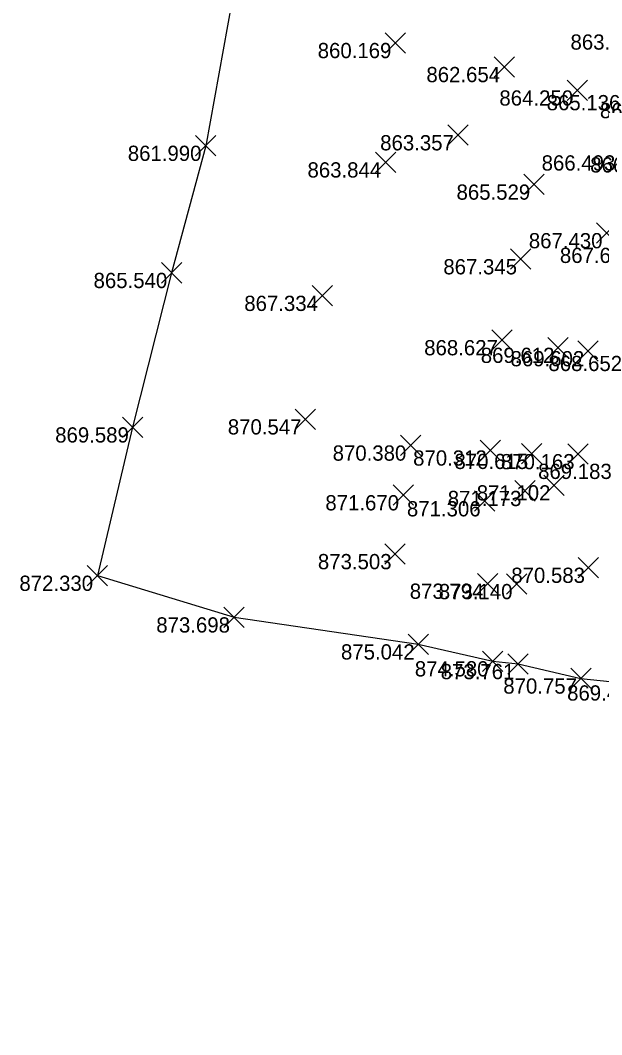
# Model space of a CAD drawing. Extents: x 2228183 to 2230895, y 679226 to 682223.
# Drawn here: x 2228195.6 to 2228233.8, y 680376.3 to 680442.9 of the extents above; entities that cross this region are included whole.
import ezdxf

# ---------------------------------------------------------------- set-up
doc = ezdxf.new("R2010")
doc.units = 0
for name, color, linetype in [('SC_Scratch1', 7, 'Continuous'), ('SV_X_Random_Point', 7, 'Continuous'), ('SV_X_Terrain_Boundary', 7, 'Continuous')]:
    doc.layers.add(name, color=color, linetype=linetype)

msp = doc.modelspace()

# ---------------------------------------------------------------- linework, layer by layer
at = {"layer": 'SV_X_Random_Point'}
for p, q in [((2228219.56, 680440.706), (2228220.894, 680442.041)), ((2228219.56, 680442.041), (2228220.894, 680440.706)), ((2228226.73, 680439.129), (2228228.064, 680440.464)), ((2228226.73, 680440.464), (2228228.064, 680439.129)), ((2228231.511, 680437.592), (2228232.845, 680438.927)), ((2228231.511, 680438.927), (2228232.845, 680437.592)), ((2228223.671, 680434.652), (2228225.005, 680435.987)), ((2228223.671, 680435.987), (2228225.005, 680434.652)), ((2228207.128, 680433.96), (2228208.462, 680435.295)), ((2228207.128, 680435.295), (2228208.462, 680433.96)), ((2228218.927, 680432.871), (2228220.261, 680434.206)), ((2228218.927, 680434.206), (2228220.261, 680432.871)), ((2228228.669, 680431.414), (2228230.003, 680432.749)), ((2228228.669, 680432.749), (2228230.003, 680431.414)), ((2228233.443, 680428.225), (2228234.777, 680429.56)), ((2228233.443, 680429.56), (2228234.777, 680428.225)), ((2228227.79, 680426.514), (2228229.124, 680427.849)), ((2228227.79, 680427.849), (2228229.124, 680426.514)), ((2228204.882, 680425.614), (2228206.216, 680426.949)), ((2228204.882, 680426.949), (2228206.216, 680425.614)), ((2228214.779, 680424.111), (2228216.113, 680425.446)), ((2228214.779, 680425.446), (2228216.113, 680424.111)), ((2228226.559, 680421.2), (2228227.893, 680422.535)), ((2228226.559, 680422.535), (2228227.893, 680421.2)), ((2228230.248, 680420.699), (2228231.582, 680422.034)), ((2228230.248, 680422.034), (2228231.582, 680420.699)), ((2228232.205, 680420.479), (2228233.539, 680421.814)), ((2228232.205, 680421.814), (2228233.539, 680420.479)), ((2228213.672, 680416.003), (2228215.006, 680417.338)), ((2228213.672, 680417.338), (2228215.006, 680416.003)), ((2228202.333, 680415.474), (2228203.667, 680416.809)), ((2228202.333, 680416.809), (2228203.667, 680415.474)), ((2228220.57, 680414.284), (2228221.904, 680415.619)), ((2228220.57, 680415.619), (2228221.904, 680414.284)), ((2228225.81, 680413.959), (2228227.144, 680415.294)), ((2228225.81, 680415.294), (2228227.144, 680413.959)), ((2228228.518, 680413.737), (2228229.852, 680415.072)), ((2228228.518, 680415.072), (2228229.852, 680413.737)), ((2228231.561, 680413.719), (2228232.895, 680415.054)), ((2228231.561, 680415.054), (2228232.895, 680413.719)), ((2228228.073, 680411.304), (2228229.407, 680412.639)), ((2228228.073, 680412.639), (2228229.407, 680411.304)), ((2228229.986, 680411.671), (2228231.32, 680413.006)), ((2228229.986, 680413.006), (2228231.32, 680411.671)), ((2228220.092, 680411.02), (2228221.426, 680412.355)), ((2228220.092, 680412.355), (2228221.426, 680411.02)), ((2228225.434, 680410.627), (2228226.768, 680411.962)), ((2228225.434, 680411.962), (2228226.768, 680410.627)), ((2228219.552, 680407.158), (2228220.886, 680408.493)), ((2228219.552, 680408.493), (2228220.886, 680407.158)), ((2228232.243, 680406.26), (2228233.577, 680407.595)), ((2228232.243, 680407.595), (2228233.577, 680406.26)), ((2228200.015, 680405.736), (2228201.349, 680407.071)), ((2228200.015, 680407.071), (2228201.349, 680405.736)), ((2228225.638, 680405.216), (2228226.972, 680406.551)), ((2228225.638, 680406.551), (2228226.972, 680405.216)), ((2228227.536, 680405.191), (2228228.87, 680406.526)), ((2228227.536, 680406.526), (2228228.87, 680405.191)), ((2228208.983, 680403.002), (2228210.317, 680404.337)), ((2228208.983, 680404.337), (2228210.317, 680403.002)), ((2228221.075, 680401.231), (2228222.409, 680402.566)), ((2228221.075, 680402.566), (2228222.409, 680401.231)), ((2228225.964, 680400.12), (2228227.298, 680401.455)), ((2228225.964, 680401.455), (2228227.298, 680400.12)), ((2228227.629, 680399.94), (2228228.963, 680401.275)), ((2228227.629, 680401.275), (2228228.963, 680399.94)), ((2228231.75, 680398.991), (2228233.084, 680400.326)), ((2228231.75, 680400.326), (2228233.084, 680398.991))]:
    msp.add_line(p, q, dxfattribs=at)
at = {"layer": 'SV_X_Terrain_Boundary'}
for points in [[(2228219.411, 680529.247), (2228217.574, 680519.169), (2228217.809, 680511.512), (2228216.826, 680504.223), (2228214.656, 680486.931), (2228213.909, 680475.664), (2228214.292, 680470.108), (2228212.955, 680461.42), (2228211.821, 680456.822), (2228210.919, 680451.97), (2228207.795, 680434.627), (2228205.549, 680426.281), (2228203, 680416.141), (2228200.682, 680406.403)], [(2228200.682, 680406.403), (2228209.65, 680403.669), (2228221.742, 680401.898), (2228226.631, 680400.787), (2228228.296, 680400.607), (2228232.417, 680399.658), (2228236.631, 680399.204), (2228242.224, 680398.608), (2228245.011, 680398.302), (2228246.89, 680398.302), (2228247.363, 680398.195), (2228248.152, 680398.096), (2228248.769, 680398.124), (2228250.307, 680398.124), (2228256.103, 680397.505), (2228261.512, 680396.621), (2228262.98, 680396.337), (2228264.719, 680396.078), (2228261.054, 680370.168)]]:
    msp.add_lwpolyline(points, dxfattribs=at)

# ---------------------------------------------------------------- texts
at = {"layer": 'SC_Scratch1'}
for s, p in [('863.395', (2228231.73, 680440.932)), ('860.169', (2228215.143, 680440.373)), ('862.654', (2228222.275, 680438.796)), ('864.250', (2228227.064, 680437.259)), ('865.136', (2228230.168, 680436.952)), ('865.402', (2228233.661, 680436.432)), ('863.357', (2228219.242, 680434.319)), ('861.990', (2228202.681, 680433.627)), ('866.493', (2228229.837, 680432.995)), ('866.582', (2228233.024, 680432.868)), ('863.844', (2228214.472, 680432.538)), ('865.529', (2228224.252, 680431.081)), ('867.430', (2228228.996, 680427.892)), ('867.688', (2228231.034, 680426.929)), ('867.345', (2228223.387, 680426.181)), ('865.540', (2228200.435, 680425.281)), ('867.334', (2228210.324, 680423.778)), ('868.627', (2228222.13, 680420.867)), ('869.612', (2228225.842, 680420.366)), ('869.602', (2228227.799, 680420.146)), ('868.652', (2228230.282, 680419.833)), ('870.547', (2228209.243, 680415.67)), ('869.589', (2228197.916, 680415.141)), ('870.380', (2228216.123, 680413.951)), ('870.312', (2228221.404, 680413.626)), ('870.615', (2228224.115, 680413.404)), ('870.163', (2228227.164, 680413.386)), ('869.183', (2228229.605, 680412.749)), ('871.173', (2228223.676, 680410.971)), ('871.102', (2228225.58, 680411.338)), ('871.670', (2228215.645, 680410.687)), ('871.306', (2228220.997, 680410.294)), ('873.503', (2228215.155, 680406.825)), ('872.330', (2228195.568, 680405.403)), ('870.583', (2228227.846, 680405.927)), ('873.794', (2228221.183, 680404.883)), ('873.140', (2228223.089, 680404.858)), ('873.698', (2228204.55, 680402.669)), ('875.042', (2228216.669, 680400.898)), ('874.580', (2228221.517, 680399.787)), ('873.761', (2228223.214, 680399.607)), ('870.757', (2228227.321, 680398.658)), ('869.474', (2228231.509, 680398.204))]:
    msp.add_text(s, height=1, dxfattribs=at).set_placement(p)

doc.saveas('drawing.dxf')
